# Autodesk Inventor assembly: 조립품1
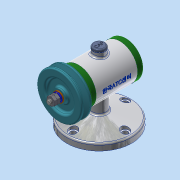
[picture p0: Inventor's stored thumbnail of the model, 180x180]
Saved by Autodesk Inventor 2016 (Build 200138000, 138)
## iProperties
Created: 2018-12
Part Number: 조립품1
Material: 일반
Document SubType Name: Assembly
Designer: 3sil_cad018
Author: 3sil_cad018
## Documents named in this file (15)
- C:\Users\3sil_cad018\Desktop\481207V1002\조립품1.iam
- C:\Users\3sil_cad018\Desktop\481207V1002\본체.ipt
- C:\Users\3sil_cad018\Desktop\481207V1002\V벨트풀리.ipt
- C:\Users\3sil_cad018\Desktop\481207V1002\고무캡.ipt
- C:\Users\3sil_cad018\Desktop\481207V1002\뒤커버.ipt
- C:\Users\3sil_cad018\Desktop\481207V1002\베어링 15 x 32 x 9.ipt
- C:\Users\3sil_cad018\Desktop\481207V1002\볼트 M4 x 12.ipt
- C:\Users\3sil_cad018\Desktop\481207V1002\스프링와셔 8.ipt
- C:\Users\3sil_cad018\Desktop\481207V1002\앞커버.ipt
- C:\Users\3sil_cad018\Desktop\481207V1002\오일 실 15 25 7.ipt
- C:\Users\3sil_cad018\Desktop\481207V1002\축.ipt
- C:\Users\3sil_cad018\Desktop\481207V1002\키 3 x 3 x 12.ipt
- C:\Users\3sil_cad018\Desktop\481207V1002\와셔 8x17.ipt
- C:\Users\3sil_cad018\Desktop\481207V1002\너트 M8.ipt
- 너트 M8.ipt
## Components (2 placed, 2 different names)
1. V벨트풀리:1 — 각도:3
2. 고무캡:1 — 각도:7
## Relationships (2: Angle 2)
- 각도:3 [Angle]: V벨트풀리:1
- 각도:7 [Angle]: 고무캡:1
